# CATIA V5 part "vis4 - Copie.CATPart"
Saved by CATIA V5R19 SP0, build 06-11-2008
Part number: vis4_rouleau
Definition: NONE
Nomenclature: 1
Source: Unknown
Description: PART-1-DESC
Bounding box of the stored display mesh (mm): x -3.5 to 3.5, y -3.329 to 3.329, z -30 to 4
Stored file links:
  G:\EU_thinkMotion\CFAO_2010\MMS_groupe3\MMS_groupe3\A reprendre\ftixier\florent-tixier\florent-tixier\vis4 - Copie.CATPart
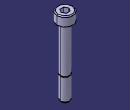
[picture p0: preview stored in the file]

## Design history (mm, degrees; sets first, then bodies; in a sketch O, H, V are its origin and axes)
Set1
  Sketch1 on xy-plane, origin (0, 0, 0), H (1, 0, 0), V (0, 1, 0)
    circle A1 centre (0, 0) radius 2
    reference projected arc E1 centre (0, 0) radius 3.1 from (-3.1, 0) to (3.1, 0) ccw from edge [face of Solid1 | face of Solid1]
    radius A1 = 2
    concentricity: A1 E1
Body1 "1" (main body)
  Solid1: solid without history
  Pad1: profile Sketch1, direction (0, 0, -1), length 60
  Sketch2 on zx-plane, origin (0, 0, 0), H (-1, 0, 0), V (0, 0, 1)
    circle A1 centre (2, -20) radius 0.1
    point P1 (2, -20)
    reference projected line E1 through (0, 0) direction (0, 1) from axis of face of Pad1
    distance P1 E1 = 2
    radius A1 = 0.1
    distance P1 H = 20
  Groove1: profile Sketch2, axis axis of face of Pad1, angle 360
  Chamfer1: length 0.3, angle 60, on edge [end face of Pad1 | face of Pad1]
  Sketch3 on yz-plane, origin (0, 0, 0), H (0, 1, 0), V (0, 0, 1)
    line L1 (-19.395, -30) -> (33.8168, -30)
    line L2 (33.8168, -30) -> (33.8168, -66.4537)
    line L3 (33.8168, -66.4537) -> (-19.395, -66.4537)
    line L4 (-19.395, -66.4537) -> (-19.395, -30)
    distance L1 H = 30
    horizontal: L1 H, L3 H
    vertical: L2 V, L4 V
  Pocket1: profile Sketch3, direction (-1, 0, 0), length 60, mirrored extent
  Chamfer2: length 0.3, angle 60, on face of Pocket1 from Sketch3.L1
